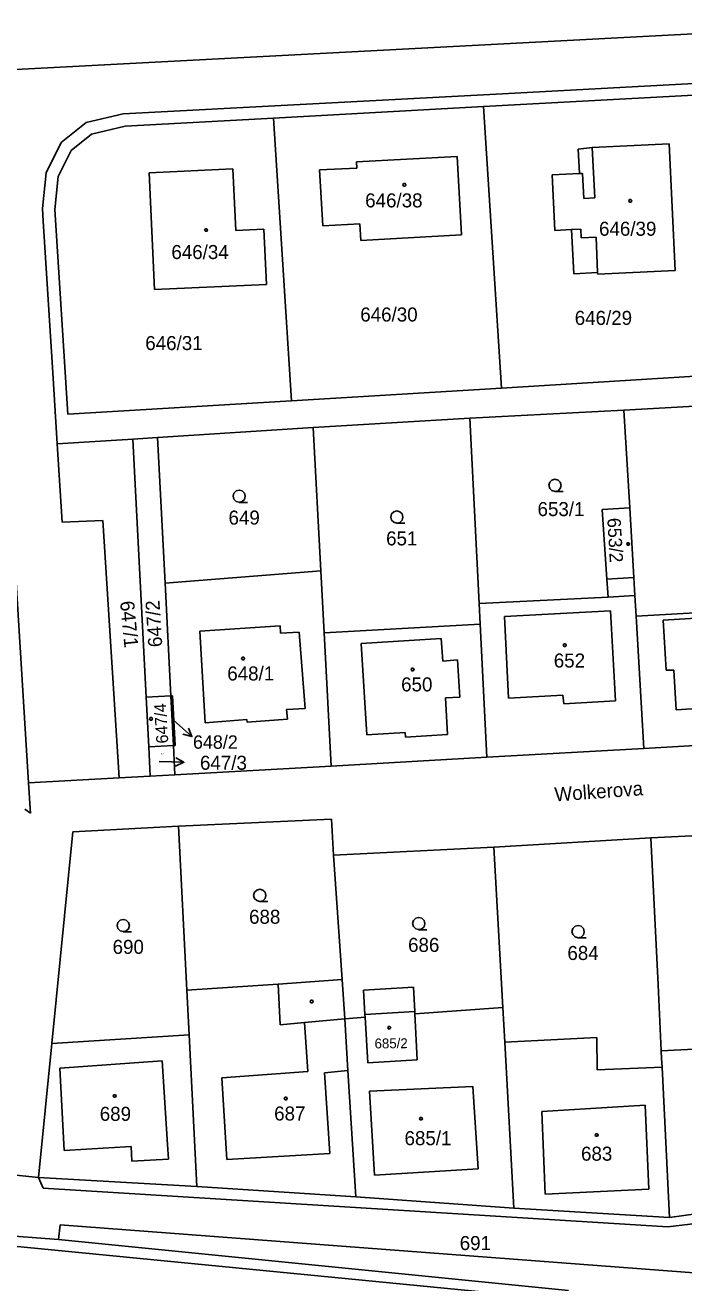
# Model space of a CAD drawing. Extents: x -621797 to -620972, y -1175539 to -1174697.
# Drawn here: x -621151.7 to -621071.9, y -1175130.5 to -1174978.1 of the extents above; entities that cross this region are included whole.
import ezdxf

# ---------------------------------------------------------------- set-up
doc = ezdxf.new("R2010")
doc.units = 0
for name, color, linetype in [('INZ mimo EON - nadz', 7, 'Continuous'), ('Rozvod plynu EON', 7, 'Continuous'), ('SDEL EON', 7, 'Continuous'), ('SDEL EON - popis', 7, 'Continuous'), ('Silnoproud EON', 7, 'Continuous'), ('Silnoproud EON - popis', 7, 'Continuous')]:
    doc.layers.add(name, color=color, linetype=linetype)

msp = doc.modelspace()

# ---------------------------------------------------------------- linework, layer by layer
at = {"layer": 'INZ mimo EON - nadz'}
for p, q in [((-621133.75, -1175062.33), (-621133.72, -1175062.36)), ((-621131.477, -1175064.353), (-621133.72, -1175062.36)), ((-621132.442, -1175067.466), (-621135.44, -1175067.36))]:
    msp.add_line(p, q, dxfattribs=at)
for points in [[(-621131.893, -1175063.315), (-621131.477, -1175064.353), (-621132.557, -1175064.062)], [(-621133.424, -1175066.931), (-621132.442, -1175067.466), (-621133.459, -1175067.93)]]:
    msp.add_lwpolyline(points, dxfattribs=at)
at = {"layer": 'Rozvod plynu EON'}
for points in [[(-621105.63, -1174997.33), (-621105.54, -1174997.48), (-621105.63, -1174997.63), (-621105.81, -1174997.63), (-621105.9, -1174997.48), (-621105.81, -1174997.33)], [(-621078.26, -1174999.28), (-621078.17, -1174999.43), (-621078.26, -1174999.58), (-621078.44, -1174999.58), (-621078.53, -1174999.43), (-621078.44, -1174999.28)], [(-621129.66, -1175002.82), (-621129.57, -1175002.97), (-621129.66, -1175003.12), (-621129.84, -1175003.12), (-621129.93, -1175002.97), (-621129.84, -1175002.82)], [(-621078.51, -1175040.86), (-621078.42, -1175041.01), (-621078.51, -1175041.16), (-621078.69, -1175041.16), (-621078.78, -1175041.01), (-621078.69, -1175040.86)], [(-621086.19, -1175053.12), (-621086.1, -1175053.27), (-621086.19, -1175053.42), (-621086.37, -1175053.42), (-621086.46, -1175053.27), (-621086.37, -1175053.12)], [(-621125.17, -1175054.74), (-621125.08, -1175054.89), (-621125.17, -1175055.04), (-621125.35, -1175055.04), (-621125.44, -1175054.89), (-621125.35, -1175054.74)], [(-621104.64, -1175056.07), (-621104.55, -1175056.22), (-621104.64, -1175056.37), (-621104.82, -1175056.37), (-621104.91, -1175056.22), (-621104.82, -1175056.07)], [(-621136.34, -1175062.04), (-621136.25, -1175062.19), (-621136.34, -1175062.34), (-621136.52, -1175062.34), (-621136.61, -1175062.19), (-621136.52, -1175062.04)], [(-621116.87, -1175096.3), (-621116.78, -1175096.45), (-621116.87, -1175096.6), (-621117.05, -1175096.6), (-621117.14, -1175096.45), (-621117.05, -1175096.3)], [(-621107.47, -1175099.48), (-621107.38, -1175099.63), (-621107.47, -1175099.78), (-621107.65, -1175099.78), (-621107.74, -1175099.63), (-621107.65, -1175099.48)], [(-621140.75, -1175107.74), (-621140.66, -1175107.89), (-621140.75, -1175108.04), (-621140.93, -1175108.04), (-621141.02, -1175107.89), (-621140.93, -1175107.74)], [(-621120, -1175108.05), (-621119.91, -1175108.2), (-621120, -1175108.35), (-621120.18, -1175108.35), (-621120.27, -1175108.2), (-621120.18, -1175108.05)], [(-621103.62, -1175110.5), (-621103.53, -1175110.65), (-621103.62, -1175110.8), (-621103.8, -1175110.8), (-621103.89, -1175110.65), (-621103.8, -1175110.5)], [(-621082.32, -1175112.48), (-621082.23, -1175112.63), (-621082.32, -1175112.78), (-621082.5, -1175112.78), (-621082.59, -1175112.63), (-621082.5, -1175112.48)]]:
    msp.add_lwpolyline(points, close=True, dxfattribs=at)
at = {"layer": 'SDEL EON'}
for points in [[(-621087.46, -1175034.64), (-621087.84, -1175034.54), (-621088.11, -1175034.27), (-621088.21, -1175033.9), (-621088.11, -1175033.53), (-621087.84, -1175033.26), (-621087.47, -1175033.16), (-621087.1, -1175033.26), (-621086.83, -1175033.53), (-621086.73, -1175033.91), (-621086.83, -1175034.29), (-621087.1, -1175034.56), (-621087.48, -1175034.66), (-621086.48, -1175034.66)], [(-621125.73, -1175035.96), (-621126.11, -1175035.86), (-621126.38, -1175035.59), (-621126.48, -1175035.22), (-621126.38, -1175034.85), (-621126.11, -1175034.58), (-621125.74, -1175034.48), (-621125.37, -1175034.58), (-621125.1, -1175034.85), (-621125, -1175035.23), (-621125.1, -1175035.61), (-621125.37, -1175035.88), (-621125.75, -1175035.98), (-621124.75, -1175035.98)], [(-621106.63, -1175038.48), (-621107.01, -1175038.38), (-621107.28, -1175038.11), (-621107.38, -1175037.74), (-621107.28, -1175037.37), (-621107.01, -1175037.1), (-621106.64, -1175037), (-621106.27, -1175037.1), (-621106, -1175037.37), (-621105.9, -1175037.75), (-621106, -1175038.13), (-621106.27, -1175038.4), (-621106.65, -1175038.5), (-621105.65, -1175038.5)], [(-621123.24, -1175084.33), (-621123.62, -1175084.23), (-621123.89, -1175083.96), (-621123.99, -1175083.59), (-621123.89, -1175083.22), (-621123.62, -1175082.95), (-621123.25, -1175082.85), (-621122.88, -1175082.95), (-621122.61, -1175083.22), (-621122.51, -1175083.6), (-621122.61, -1175083.98), (-621122.88, -1175084.25), (-621123.26, -1175084.35), (-621122.26, -1175084.35)], [(-621139.78, -1175087.98), (-621140.16, -1175087.88), (-621140.43, -1175087.61), (-621140.53, -1175087.24), (-621140.43, -1175086.87), (-621140.16, -1175086.6), (-621139.79, -1175086.5), (-621139.42, -1175086.6), (-621139.15, -1175086.87), (-621139.05, -1175087.25), (-621139.15, -1175087.63), (-621139.42, -1175087.9), (-621139.8, -1175088), (-621138.8, -1175088)], [(-621103.97, -1175087.74), (-621104.35, -1175087.64), (-621104.62, -1175087.37), (-621104.72, -1175087), (-621104.62, -1175086.63), (-621104.35, -1175086.36), (-621103.98, -1175086.26), (-621103.61, -1175086.36), (-621103.34, -1175086.63), (-621103.24, -1175087.01), (-621103.34, -1175087.39), (-621103.61, -1175087.66), (-621103.99, -1175087.76), (-621102.99, -1175087.76)], [(-621084.66, -1175088.72), (-621085.04, -1175088.62), (-621085.31, -1175088.35), (-621085.41, -1175087.98), (-621085.31, -1175087.61), (-621085.04, -1175087.34), (-621084.67, -1175087.24), (-621084.3, -1175087.34), (-621084.03, -1175087.61), (-621083.93, -1175087.99), (-621084.03, -1175088.37), (-621084.3, -1175088.64), (-621084.68, -1175088.74), (-621083.68, -1175088.74)]]:
    msp.add_lwpolyline(points, dxfattribs=at)
at = {"layer": 'SDEL EON - popis'}
for p, q in [((-621082.64, -1174999.07), (-621082.96, -1174992.95)), ((-621084.13, -1174996.11), (-621084.51, -1174996.13)), ((-621083.98, -1174999.14), (-621084.13, -1174996.11)), ((-621083.98, -1174999.14), (-621082.64, -1174999.07)), ((-621084.34, -1175002.86), (-621085.46, -1175002.91)), ((-621084.29, -1175003.89), (-621084.34, -1175002.86)), ((-621082.47, -1175003.82), (-621084.29, -1175003.89)), ((-621082.3, -1175008.12), (-621082.47, -1175003.82)), ((-621081.19, -1175045.26), (-621077.91, -1175045.06)), ((-621093.58, -1175049.8), (-621080.74, -1175049.11)), ((-621093.09, -1175059.68), (-621093.58, -1175049.8)), ((-621080.74, -1175049.11), (-621080.14, -1175060.03)), ((-621074.36, -1175050.24), (-621063.88, -1175049.59)), ((-621130.51, -1175051.56), (-621120.78, -1175050.93)), ((-621129.88, -1175062.68), (-621130.51, -1175051.56)), ((-621120.78, -1175050.93), (-621120.73, -1175051.82)), ((-621073.98, -1175056.31), (-621074.36, -1175050.24)), ((-621120.73, -1175051.82), (-621118.47, -1175051.71)), ((-621118.47, -1175051.71), (-621117.76, -1175060.93)), ((-621110.94, -1175053.08), (-621101.25, -1175052.47)), ((-621110.28, -1175064.15), (-621110.94, -1175053.08)), ((-621101.25, -1175052.47), (-621101.05, -1175055.19)), ((-621101.05, -1175055.19), (-621099.28, -1175055.06)), ((-621099.28, -1175055.06), (-621099.01, -1175059.58)), ((-621073.08, -1175056.29), (-621073.98, -1175056.31)), ((-621072.77, -1175061.1), (-621073.08, -1175056.29)), ((-621099.01, -1175059.58), (-621100.75, -1175059.66)), ((-621100.75, -1175059.66), (-621100.51, -1175064.1)), ((-621086.52, -1175059.33), (-621093.09, -1175059.68)), ((-621086.4, -1175060.37), (-621086.52, -1175059.33)), ((-621080.14, -1175060.03), (-621086.4, -1175060.37)), ((-621063.81, -1175060.53), (-621072.77, -1175061.1)), ((-621124.81, -1175062.29), (-621129.88, -1175062.68)), ((-621124.79, -1175062.6), (-621124.81, -1175062.29)), ((-621119.88, -1175062.25), (-621124.79, -1175062.6)), ((-621117.76, -1175060.93), (-621120.02, -1175061.07)), ((-621120.02, -1175061.07), (-621119.88, -1175062.25)), ((-621105.62, -1175063.84), (-621110.28, -1175064.15)), ((-621105.57, -1175064.42), (-621105.62, -1175063.84)), ((-621100.51, -1175064.1), (-621105.57, -1175064.42)), ((-621121.01, -1175094.36), (-621120.78, -1175099.26)), ((-621117.82, -1175098.98), (-621112.95, -1175098.53)), ((-621110.51, -1175098.02), (-621104.46, -1175097.65)), ((-621120.78, -1175099.26), (-621117.82, -1175098.98)), ((-621117.82, -1175098.98), (-621117.43, -1175104.93)), ((-621147.47, -1175104.52), (-621135.09, -1175103.62)), ((-621146.95, -1175114.49), (-621147.47, -1175104.52)), ((-621135.09, -1175103.62), (-621134.41, -1175113.79)), ((-621117.43, -1175104.93), (-621127.86, -1175105.68)), ((-621115.41, -1175105.09), (-621112.56, -1175104.83)), ((-621127.86, -1175105.68), (-621127.25, -1175115.6)), ((-621114.76, -1175114.87), (-621115.41, -1175105.09)), ((-621109.94, -1175107.33), (-621097.41, -1175106.73)), ((-621109.35, -1175117.5), (-621109.94, -1175107.33)), ((-621097.41, -1175106.73), (-621096.79, -1175116.74)), ((-621089.07, -1175109.78), (-621076.53, -1175109.02)), ((-621076.53, -1175109.02), (-621076.08, -1175119.17)), ((-621088.66, -1175119.78), (-621089.07, -1175109.78)), ((-621138.84, -1175114.04), (-621146.95, -1175114.49)), ((-621138.74, -1175115.81), (-621138.84, -1175114.04)), ((-621134.41, -1175113.79), (-621134.29, -1175115.56)), ((-621134.29, -1175115.56), (-621138.74, -1175115.81)), ((-621127.25, -1175115.6), (-621114.76, -1175114.87)), ((-621096.79, -1175116.74), (-621109.35, -1175117.5)), ((-621149.5, -1175119.07), (-621150.08, -1175117.76)), ((-621073.79, -1175123.74), (-621149.5, -1175119.07)), ((-621076.08, -1175119.17), (-621088.66, -1175119.78)), ((-621034.32, -1175119.19), (-621073.79, -1175123.74)), ((-621197.6, -1175121.77), (-621081.88, -1175133.05)), ((-621147.63, -1175125.29), (-621147.44, -1175123.51)), ((-621147.44, -1175123.51), (-621069.02, -1175129.45))]:
    msp.add_line(p, q, dxfattribs=at)
at = {"layer": 'Silnoproud EON'}
for p, q in [((-621049.45, -1174978.08), (-621095.2, -1174980.47)), ((-621095.2, -1174980.47), (-621156.69, -1174983.71)), ((-621094.58, -1174986.49), (-621050.19, -1174984.09)), ((-621139.79, -1174988.88), (-621094.58, -1174986.49)), ((-621070.66, -1174986.61), (-621096.12, -1174988)), ((-621144.29, -1174989.94), (-621139.79, -1174988.88)), ((-621096.12, -1174988), (-621121.58, -1174989.39)), ((-621093.95, -1175022.11), (-621096.12, -1174988)), ((-621147.32, -1174992.35), (-621144.29, -1174989.94)), ((-621143.62, -1174991.33), (-621139.54, -1174990.37)), ((-621139.54, -1174990.37), (-621121.58, -1174989.39)), ((-621119.4, -1175023.65), (-621121.58, -1174989.39)), ((-621146.11, -1174993.31), (-621143.62, -1174991.33)), ((-621149.14, -1174996.02), (-621147.32, -1174992.35)), ((-621147.67, -1174996.49), (-621146.11, -1174993.31)), ((-621084.65, -1174993.15), (-621082.96, -1174992.95)), ((-621084.65, -1174993.15), (-621084.51, -1174996.13)), ((-621082.96, -1174992.95), (-621073.64, -1174992.53)), ((-621072.92, -1175007.87), (-621073.64, -1174992.53)), ((-621111.51, -1174994.71), (-621099.31, -1174994.04)), ((-621111.47, -1174995.47), (-621111.51, -1174994.71)), ((-621099.31, -1174994.04), (-621098.78, -1175003.53)), ((-621149.59, -1175000.34), (-621149.14, -1174996.02)), ((-621148.08, -1175000.46), (-621147.67, -1174996.49)), ((-621136.66, -1174996.02), (-621126.5, -1174995.55)), ((-621136, -1175010.19), (-621136.66, -1174996.02)), ((-621126.5, -1174995.55), (-621126.14, -1175003.03)), ((-621115.99, -1174995.67), (-621111.47, -1174995.47)), ((-621115.61, -1175002.46), (-621115.99, -1174995.67)), ((-621084.51, -1174996.13), (-621087.79, -1174996.27)), ((-621087.48, -1175003.01), (-621087.79, -1174996.27)), ((-621149.49, -1175001.91), (-621149.59, -1175000.34)), ((-621148.08, -1175000.46), (-621146.5, -1175025.29)), ((-621148.38, -1175019.61), (-621149.49, -1175001.91)), ((-621126.14, -1175003.03), (-621122.76, -1175002.87)), ((-621122.76, -1175002.87), (-621122.45, -1175009.56)), ((-621111.11, -1175002.21), (-621115.61, -1175002.46)), ((-621111, -1175004.24), (-621111.11, -1175002.21)), ((-621098.78, -1175003.53), (-621111, -1175004.24)), ((-621085.46, -1175002.91), (-621087.48, -1175003.01)), ((-621085.46, -1175002.91), (-621085.19, -1175008.27)), ((-621085.19, -1175008.27), (-621082.3, -1175008.12)), ((-621082.3, -1175008.12), (-621082.29, -1175008.32)), ((-621082.29, -1175008.32), (-621072.92, -1175007.87)), ((-621122.45, -1175009.56), (-621136, -1175010.19)), ((-621147.8, -1175028.87), (-621148.38, -1175019.61)), ((-621068.49, -1175020.56), (-621093.95, -1175022.11)), ((-621093.95, -1175022.11), (-621119.4, -1175023.65)), ((-621146.5, -1175025.29), (-621119.4, -1175023.65)), ((-621060.25, -1175023.7), (-621079.12, -1175024.81)), ((-621079.12, -1175024.81), (-621097.8, -1175025.77)), ((-621079.12, -1175024.81), (-621078.41, -1175036.64)), ((-621116.76, -1175026.89), (-621135.64, -1175028.1)), ((-621097.8, -1175025.77), (-621116.76, -1175026.89)), ((-621116.76, -1175026.89), (-621115.84, -1175044.27)), ((-621097.8, -1175025.77), (-621096.67, -1175048.24)), ((-621138.63, -1175028.29), (-621147.8, -1175028.87)), ((-621135.64, -1175028.1), (-621138.63, -1175028.29)), ((-621138.63, -1175028.29), (-621137.01, -1175059.57)), ((-621135.64, -1175028.1), (-621134.72, -1175045.77)), ((-621153.77, -1175029.25), (-621151.28, -1175069.94)), ((-621147.21, -1175038.36), (-621147.8, -1175028.87)), ((-621078.41, -1175036.64), (-621081.75, -1175036.84)), ((-621081.75, -1175036.84), (-621081.19, -1175045.26)), ((-621078.41, -1175036.64), (-621077.91, -1175045.06)), ((-621142.25, -1175038.15), (-621147.21, -1175038.36)), ((-621140.29, -1175069.34), (-621142.25, -1175038.15)), ((-621134.72, -1175045.77), (-621115.84, -1175044.27)), ((-621115.84, -1175044.27), (-621115.45, -1175051.76)), ((-621081.19, -1175045.26), (-621081.04, -1175047.44)), ((-621077.91, -1175045.06), (-621077.78, -1175047.27)), ((-621134.72, -1175045.77), (-621134.01, -1175059.41)), ((-621096.67, -1175048.24), (-621081.04, -1175047.44)), ((-621096.67, -1175048.24), (-621096.54, -1175050.74)), ((-621081.04, -1175047.44), (-621077.78, -1175047.27)), ((-621077.78, -1175047.27), (-621077.63, -1175049.77)), ((-621077.63, -1175049.77), (-621058.8, -1175048.66)), ((-621077.63, -1175049.77), (-621076.68, -1175065.79)), ((-621115.45, -1175051.76), (-621096.54, -1175050.74)), ((-621096.54, -1175050.74), (-621095.73, -1175066.83)), ((-621115.45, -1175051.76), (-621114.6, -1175067.93)), ((-621137.01, -1175059.57), (-621134.01, -1175059.41)), ((-621137.01, -1175059.57), (-621136.7, -1175065.6)), ((-621134.01, -1175059.41), (-621133.81, -1175059.4)), ((-621134.01, -1175059.41), (-621133.7, -1175065.44)), ((-621133.81, -1175059.4), (-621133.5, -1175065.43)), ((-621057.87, -1175064.7), (-621076.68, -1175065.79)), ((-621133.7, -1175065.44), (-621136.7, -1175065.6)), ((-621136.7, -1175065.6), (-621136.52, -1175069.13)), ((-621133.5, -1175065.43), (-621133.7, -1175065.44)), ((-621133.7, -1175065.44), (-621133.52, -1175068.97)), ((-621095.73, -1175066.83), (-621114.6, -1175067.93)), ((-621076.68, -1175065.79), (-621095.73, -1175066.83)), ((-621114.6, -1175067.93), (-621133.52, -1175068.97)), ((-621140.29, -1175069.34), (-621151.28, -1175069.94)), ((-621136.52, -1175069.13), (-621140.29, -1175069.34)), ((-621133.52, -1175068.97), (-621136.52, -1175069.13)), ((-621151.28, -1175069.94), (-621151.05, -1175073.63)), ((-621151.05, -1175073.63), (-621151.72, -1175073.16)), ((-621114.55, -1175074.36), (-621133.09, -1175075.22)), ((-621114.3, -1175078.72), (-621114.55, -1175074.36)), ((-621145.89, -1175075.9), (-621148.46, -1175101.54)), ((-621133.09, -1175075.22), (-621145.89, -1175075.9)), ((-621132.09, -1175095.08), (-621133.09, -1175075.22)), ((-621057.04, -1175075.7), (-621075.86, -1175076.61)), ((-621075.86, -1175076.61), (-621094.88, -1175077.75)), ((-621074.98, -1175094.42), (-621075.86, -1175076.61)), ((-621094.88, -1175077.75), (-621114.3, -1175078.72)), ((-621113.24, -1175093.77), (-621114.3, -1175078.72)), ((-621093.8, -1175097.17), (-621094.88, -1175077.75)), ((-621121.01, -1175094.36), (-621113.24, -1175093.77)), ((-621112.95, -1175098.53), (-621113.24, -1175093.77)), ((-621132.09, -1175095.08), (-621121.01, -1175094.36)), ((-621131.82, -1175100.48), (-621132.09, -1175095.08)), ((-621110.69, -1175095.08), (-621104.6, -1175094.7)), ((-621110.51, -1175098.02), (-621110.69, -1175095.08)), ((-621104.6, -1175094.7), (-621104.46, -1175097.65)), ((-621074.59, -1175102.41), (-621074.98, -1175094.42)), ((-621104.45, -1175097.93), (-621093.8, -1175097.17)), ((-621093.56, -1175101.36), (-621093.8, -1175097.17)), ((-621112.95, -1175098.53), (-621110.49, -1175098.35)), ((-621112.56, -1175104.83), (-621112.95, -1175098.53)), ((-621110.49, -1175098.35), (-621110.51, -1175098.02)), ((-621110.49, -1175098.35), (-621110.15, -1175103.88)), ((-621104.46, -1175097.65), (-621104.45, -1175097.93)), ((-621104.18, -1175103.51), (-621104.45, -1175097.93)), ((-621148.46, -1175101.54), (-621150.08, -1175117.76)), ((-621148.46, -1175101.54), (-621131.82, -1175100.48)), ((-621130.89, -1175118.87), (-621131.82, -1175100.48)), ((-621093.56, -1175101.36), (-621082.39, -1175100.8)), ((-621092.44, -1175121.5), (-621093.56, -1175101.36)), ((-621082.39, -1175100.8), (-621082.36, -1175104.74)), ((-621069.01, -1175102.16), (-621074.59, -1175102.41)), ((-621074.54, -1175103.36), (-621074.59, -1175102.41)), ((-621074.49, -1175104.41), (-621074.54, -1175103.36)), ((-621111.62, -1175120.13), (-621112.56, -1175104.83)), ((-621110.15, -1175103.88), (-621104.18, -1175103.51)), ((-621082.36, -1175104.74), (-621074.49, -1175104.41)), ((-621073.6, -1175122.62), (-621074.49, -1175104.41)), ((-621156.24, -1175117.16), (-621150.08, -1175117.76)), ((-621150.08, -1175117.76), (-621130.89, -1175118.87)), ((-621130.89, -1175118.87), (-621111.62, -1175120.13)), ((-621111.62, -1175120.13), (-621092.44, -1175121.5)), ((-621073.6, -1175122.62), (-621054.67, -1175120.05)), ((-621092.44, -1175121.5), (-621073.6, -1175122.62)), ((-621159.25, -1175124.41), (-621147.63, -1175125.29)), ((-621147.63, -1175125.29), (-621085.82, -1175131.48))]:
    msp.add_line(p, q, dxfattribs=at)

# ---------------------------------------------------------------- texts
at = {"layer": 'INZ mimo EON - nadz'}
for s, height, p in [('648/2', 1.62, (-621131.337, -1175065.82)), ('647/3', 1.7, (-621130.493, -1175068.37)), ('691', 1.7, (-621099.013, -1175126.57))]:
    msp.add_text(s, height=height, dxfattribs=at).set_placement(p)
msp.add_text('Wolkerova', height=1.7, rotation=4.068, dxfattribs=at).set_placement((-621087.462, -1175072.212))
at = {"layer": 'Silnoproud EON - popis'}
for s, height, p in [('646/38', 1.7, (-621110.47, -1175000.22)), ('646/39', 1.7, (-621082.129, -1175003.66)), ('646/34', 1.7, (-621133.959, -1175006.48)), ('646/30', 1.7, (-621111.066, -1175014.05)), ('646/29', 1.7, (-621085.076, -1175014.46)), ('646/31', 1.7, (-621137.121, -1175017.51)), ('653/1', 1.7, (-621089.583, -1175037.63)), ('649', 1.7, (-621127.033, -1175038.66)), ('651', 1.7, (-621107.933, -1175041.18)), ('652', 1.7, (-621087.613, -1175055.98)), ('648/1', 1.7, (-621127.183, -1175057.55)), ('650', 1.7, (-621106.113, -1175058.87)), ('647/3', 0.1, (-621135.219, -1175066.49)), ('688', 1.7, (-621124.543, -1175087.03)), ('690', 1.7, (-621141.083, -1175090.68)), ('686', 1.7, (-621105.273, -1175090.44)), ('684', 1.7, (-621085.963, -1175091.42)), ('689', 1.7, (-621142.641, -1175110.91)), ('687', 1.7, (-621121.503, -1175110.87)), ('685/1', 1.7, (-621105.703, -1175113.86)), ('683', 1.7, (-621084.313, -1175115.74))]:
    msp.add_text(s, height=height, dxfattribs=at).set_placement(p)
for s, height, rotation, p in [('653/2', 1.62, 273.35816, (-621081.133, -1175037.887)), ('647/1', 1.7, 275.42081, (-621140.176, -1175047.975)), ('647/2', 1.7, 93.6213, (-621135.053, -1175053.454)), ('647/4', 1.45, 93.39212, (-621134.329, -1175065.139)), ('648/2', 0.1, 93.04835, (-621133.739, -1175062.538)), ('685/2', 1.2, 0.51566, (-621109.328, -1175102.138))]:
    msp.add_text(s, height=height, rotation=rotation, dxfattribs=at).set_placement(p)

doc.saveas('drawing.dxf')
